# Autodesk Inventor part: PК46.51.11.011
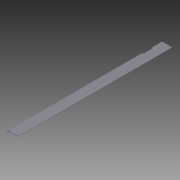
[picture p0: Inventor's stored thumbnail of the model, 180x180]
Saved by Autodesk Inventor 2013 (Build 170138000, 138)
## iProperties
Shininess: 64.0
Length Units: 11269
Angle Units: 11279
Time Units: 11290
Mass Units: 11283
Length Display Precision: 3
Angle Display Precision: 2
Compacted: True
Part Number: PК46.51.11.011
Document SubType Name: Листовой материал
Created: 2005-02
Material: Steel, Mild
Designer: =<Author>
Manufacturer: Standard
Standards Organization: Custom
Description: Side Plate
Density: 7.86 g/cm^3
Flat Pattern Width: 89.8 cm
Flat Pattern Length: 7.05239 cm
Flat Pattern Area: 633.305 cm^2
Sheet Metal Rule: По умолчанию
Mass: 983.737 g
Surface Area: 1291.03 cm^2
Volume: 125.157 cm^3
Density: 0.0
Volumn: 0.0
Area: 0.0
PropertySet Name: Model Information
Control State: 0
Master: False
Checked Out: False
Checked Out Date: 2008-10-15
Last Check In Date: 2008-10-15
Толщина: 2.000 mm
Радиус_гибки: 2.000 mm
Ширина_просечки: 2.000 mm
Глубина_просечки: 1.000 mm
Размер_высечки: 8.000 mm
Минимальный_остаток: 4.000 mm
Радиус_перехода: 2.000 mm
JacobiRadiusSize: 2.000 mm
GapSize: 2.000 mm
d0: 62.000 mm
d1: 898.000 mm
d2: 2.000 mm
d3: 2.000 mm
d4: 1.000 mm
d5: 4.000 mm
d6: 2.000 mm
d7: 10.000 mm
d8: 90.00 deg
d9: 2.000 mm
d10: 52.000 mm
d11: 9.000 mm
d12: 64.000 mm
d14: 0.00 deg
Author: PVitaliy
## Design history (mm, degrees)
node "Грань1"
node "Фланец1"
feature "Вырез1" dims "d13" = 2 (= Толщина), angle "d14" = 0 deg
body "Solid1"
sketch "Эскиз1"
  geometry: L1 (0, 0)-(62, 0); L2 (62, 0)-(62, 898); L3 (62, 898)-(0, 898); L4 (0, 898)-(0, 0)
  constraints: 8 end point, 2 parallel, 1 horizontal, 1 perpendicular, 1 other
  dimensions: "d0" = 62 distance of L1.start L1.end; "d1" = 898 distance of L3.end L1.start
feature "Пластина1" dims "Толщина" = 2
sketch "Эскиз2"
  geometry: L1 through (-449, 0) direction (-1, -3.9e-48); L2 (-898, 0)-(-898, -10); L3 (-898, -10)-(0, -10); L4 through (0, -5) direction (-1.87e-32, 1)
  constraints: 6 end point, 1 horizontal, 1 perpendicular, 1 vertical
feature "Пластина2" dims "d3" = 2 (= Ширина_просечки), "d5" = 4 (= Минимальный_остаток), "d7" = 10, angle "d8" = 90 deg, "d9" = 2 (= Радиус_гибки), "Толщина" = 2
feature "Изгиб1" dims "d3" = 2 (= Ширина_просечки), "d4" = 1 (= Глубина_просечки), "d5" = 4 (= Минимальный_остаток), "d6" = 2 (= Радиус_гибки), "d7" = 10, angle "d8" = 90 deg, "d9" = 2 (= Радиус_гибки), "Толщина" = 2, "Зазор_стыка" = 0.01
sketch "Эскиз3"
  geometry: L1 (-58, 898)-(0, 898) reference; L2 (-62, 0)-(-62, 898) reference; L3 (-62, 782)-(-53, 782); L4 (-53, 782)-(-53, 834); L5 (-53, 834)-(-62, 834)
  constraints: 6 end point, 2 perpendicular, 2 point on line, 1 parallel
  dimensions: "d10" = 52 distance of L3.end L4.end; "d11" = 9 distance between parallel lines of L2 L4; "d12" = 64 distance between parallel lines of L1 L5
node "Развертка"
feature "FlatPatternExtrusion2" dims "d0" = 2 (derived)
other parameters: "Радиус_гибки" = 2 (= Толщина), "Ширина_просечки" = 2 (= Толщина), "Глубина_просечки" = 1 (= 0.5 x Толщина), "Размер_высечки" = 8 (= 4 x Толщина), "Минимальный_остаток" = 4 (= 2 x Толщина), "Радиус_перехода" = 2 (= Радиус_гибки), "d2" = 2 (= Радиус_гибки), "JacobiRadiusSize" = 2 (= Толщина), "GapSize" = 2 (= Толщина)
